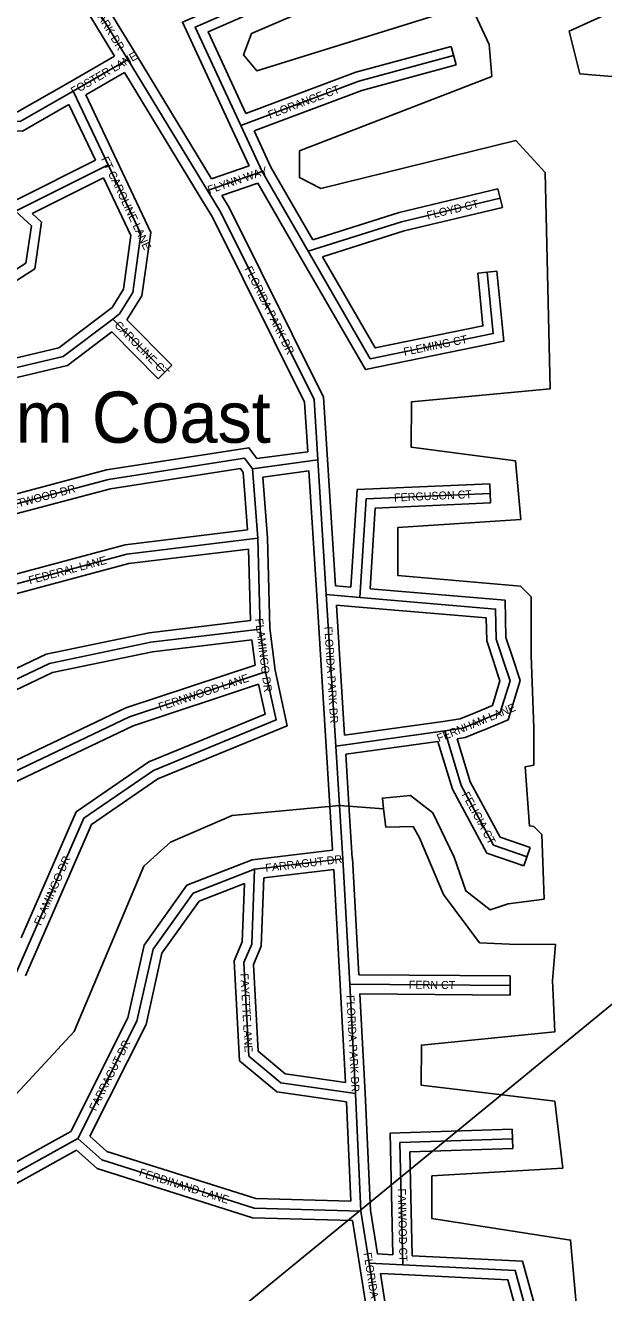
# Model space of a CAD drawing. Extents: x 457167 to 656239, y 1787309 to 1969297.
# Drawn here: x 588703 to 590509, y 1900964 to 1904923 of the extents above; entities that cross this region are included whole.
import ezdxf

# ---------------------------------------------------------------- set-up
doc = ezdxf.new("R2010")
doc.units = 0
for name, color, linetype in [('Level 1', 7, 'Continuous'), ('Level 31', 7, 'Continuous'), ('Level 32', 7, 'Continuous'), ('Level 34', 7, 'Continuous'), ('Level 44', 7, 'Continuous'), ('Level 5', 7, 'Continuous')]:
    doc.layers.add(name, color=color, linetype=linetype)

msp = doc.modelspace()

# ---------------------------------------------------------------- linework, layer by layer
at = {"layer": 'Level 1'}
msp.add_line((587876.128, 1899689.718), (592117.707, 1903161.447), dxfattribs=at)
at = {"layer": 'Level 31'}
for p, q in [((589023.1, 1904816), (588811.694, 1905163.662)), ((588852.212, 1904717.765), (589023.1, 1904816)), ((589271.277, 1904407.545), (589023.1, 1904816)), ((588961.153, 1904487.746), (588852.212, 1904717.765)), ((589442.73, 1904466.145), (589375.913, 1904610.268)), ((588672.237, 1904342.815), (588961.153, 1904487.746)), ((589271.277, 1904407.545), (589442.73, 1904466.145)), ((589442.73, 1904466.145), (589586.293, 1904217.52)), ((588975.539, 1904005.531), (589138.643, 1903840.141)), ((589412.132, 1903537.461), (589616.279, 1903565.456)), ((589642.549, 1903145.041), (589616.279, 1903565.456)), ((589412.132, 1903537.461), (589428.592, 1903320.701)), ((589436.349, 1903037.411), (589428.592, 1903320.701)), ((589671.903, 1902671.89), (589642.549, 1903145.041)), ((589642.549, 1903145.041), (589747.442, 1903135.761)), ((589452.959, 1902903.924), (589436.349, 1903037.411)), ((590012.155, 1902719.281), (589671.903, 1902671.89)), ((589683.334, 1902486.413), (589671.903, 1902671.89)), ((589693.845, 1902319.846), (589683.334, 1902486.413)), ((589418.469, 1902286.888), (589693.845, 1902319.846)), ((589715.716, 1901927.802), (589693.845, 1902319.846)), ((589734.181, 1901586.31), (589715.716, 1901927.802)), ((589715.716, 1901927.802), (590216.434, 1901923.996)), ((589750.375, 1901219.368), (589734.181, 1901586.31)), ((588057.643, 1900996.989), (588866.949, 1901446.058)), ((589776.154, 1901056.774), (589750.375, 1901219.368)), ((589808.218, 1900852.351), (589776.154, 1901056.774)), ((589776.154, 1901056.774), (589881.061, 1901051.131))]:
    msp.add_line(p, q, dxfattribs=at)
for points in [[(589375.913, 1904610.268), (589233.094, 1904917.44), (589568.101, 1905064.472), (589897.018, 1905184.975)], [(589375.913, 1904610.268), (589743.967, 1904748.516), (590040.07, 1904828.35)], [(587589.934, 1904249.169), (588194.334, 1904635.694), (588686.098, 1904622.793), (588852.212, 1904717.765)], [(588975.539, 1904005.531), (588996.232, 1904021.493), (589037.998, 1904088.326), (589063.125, 1904271.556), (588961.153, 1904487.746)], [(589616.279, 1903565.456), (589604.218, 1903753.844), (589313.433, 1904338.013), (589271.277, 1904407.545)], [(589586.293, 1904217.52), (589877.654, 1904309.724), (590185.512, 1904383.356)], [(587829.185, 1903834.538), (588079.039, 1903998.08), (588613.024, 1904122.192), (588704.687, 1904180.571), (588721.429, 1904297.27), (588672.237, 1904342.815)], [(589586.293, 1904217.52), (589779.93, 1903881.53), (590164.098, 1903960.48), (590145.364, 1904151.788)], [(587978.125, 1903575.714), (588262.027, 1903755.921), (588820.826, 1903888.356), (588975.539, 1904005.531)], [(588166.999, 1903249.181), (588461.609, 1903372.277), (588961.918, 1903504.821), (589387.396, 1903570.961), (589412.132, 1903537.461)], [(589747.442, 1903135.761), (589767.386, 1903444.092), (590153.992, 1903461.218)], [(588267.949, 1902995.536), (588619.547, 1903163.622), (589019.99, 1903271.258), (589428.592, 1903320.701)], [(589747.442, 1903135.761), (590171.152, 1903099.729), (590173.21, 1903005.542), (590195.029, 1902939.684)], [(587807.099, 1902370.559), (587826.512, 1902381.07), (588202.155, 1902655.653), (588777.76, 1902929.876), (589094.52, 1902996.21), (589436.349, 1903037.411)], [(590195.029, 1902939.684), (590216.216, 1902876.01), (590185.838, 1902776.426), (590121.254, 1902749.268)], [(588590.73, 1902526.576), (588643.919, 1902579.933), (589027.655, 1902762.874), (589452.959, 1902903.924)], [(588675.231, 1901966.051), (588885.293, 1902446.401), (589102.381, 1902595.827), (589486.069, 1902753.681), (589452.959, 1902903.924)], [(590121.254, 1902749.268), (590068.44, 1902727.543), (590012.155, 1902719.281)], [(590012.155, 1902719.281), (590063.989, 1902548.276), (590164.756, 1902362.276), (590269.604, 1902326.089)], [(588866.949, 1901446.058), (589051.054, 1901812.274), (589101.373, 1902037.276), (589226.631, 1902212.324), (589418.469, 1902286.888)], [(589734.181, 1901586.31), (589500.884, 1901619.821), (589400.889, 1901703.64), (589384.882, 1901995.308), (589409.784, 1902053.446), (589418.469, 1902286.888)], [(589750.375, 1901219.368), (589416.885, 1901228.331), (588941.858, 1901379.011), (588866.949, 1901446.058)], [(589881.061, 1901051.131), (589872.522, 1901433.333), (590223.85, 1901445.068)], [(589881.061, 1901051.131), (590232.023, 1901033.776), (590348.274, 1900612.473), (590536.846, 1900093.951), (590398.49, 1899884.376)]]:
    msp.add_lwpolyline(points, dxfattribs=at)
at = {"layer": 'Level 32'}
for p, q in [((588981.492, 1904826.684), (588786.062, 1905148.075)), ((589048.734, 1904831.587), (588855.181, 1905149.89)), ((588837.26, 1904743.773), (588981.492, 1904826.684)), ((589284.394, 1904443.731), (589048.739, 1904831.578)), ((590032.261, 1904857.316), (590047.88, 1904799.383)), ((588891.187, 1904705.563), (589012.668, 1904775.397)), ((589245.639, 1904391.966), (589012.667, 1904775.396)), ((588988.266, 1904500.586), (588891.186, 1904705.563)), ((588921.486, 1904501.41), (588838.971, 1904675.634)), ((589401.499, 1904483.756), (589348.696, 1904597.649)), ((589469.383, 1904479.982), (589416.73, 1904593.551)), ((588677.484, 1904379.009), (588921.486, 1904501.41)), ((589284.394, 1904443.731), (589401.499, 1904483.756)), ((589469.384, 1904479.982), (589600.221, 1904253.394)), ((588724.391, 1904335.412), (588947.132, 1904447.146)), ((589316.262, 1904391.214), (589429.088, 1904429.776)), ((589429.088, 1904429.776), (589560.313, 1904202.517)), ((590178.533, 1904412.535), (590192.49, 1904354.178)), ((590115.506, 1904148.865), (590175.221, 1904154.711)), ((589020.097, 1904003.074), (589160.004, 1903861.207)), ((588972.665, 1903965.718), (589117.283, 1903819.075)), ((589160.004, 1903861.207), (589117.283, 1903819.075)), ((589425.694, 1903569.601), (589584.558, 1903591.387)), ((589670.883, 1903172.651), (589646.221, 1903567.326)), ((589382.873, 1903526.582), (589396.506, 1903347.037)), ((589444.185, 1903511.573), (589588.352, 1903531.344)), ((589612.606, 1903143.183), (589588.352, 1903531.345)), ((589444.185, 1903511.573), (589458.562, 1903322.247)), ((590152.664, 1903491.19), (590155.319, 1903431.246)), ((589466.299, 1903039.677), (589458.563, 1903322.247)), ((589405.613, 1903063.923), (589399.505, 1903286.961)), ((589670.883, 1903172.651), (589719.488, 1903168.351)), ((589641.96, 1902670.032), (589612.606, 1903143.183)), ((589674.652, 1903112.082), (589744.799, 1903105.876)), ((589699.841, 1902706.071), (589674.652, 1903112.081)), ((589420.149, 1902924.649), (589410.269, 1903004.048)), ((589482.558, 1902909.014), (589466.299, 1903039.677)), ((590007.798, 1902748.963), (589699.841, 1902706.071)), ((589990.888, 1902686.027), (589703.556, 1902646.008)), ((589653.391, 1902484.567), (589641.959, 1902670.044)), ((589713.277, 1902488.258), (589703.556, 1902646.008)), ((589723.786, 1902321.736), (589713.274, 1902488.301)), ((589662.119, 1902346.264), (589653.394, 1902484.524)), ((589411.138, 1902316.225), (589662.119, 1902346.263)), ((590279.391, 1902354.448), (590259.816, 1902297.73)), ((589744.103, 1901957.587), (589723.799, 1902321.517)), ((589447.496, 1902260.146), (589665.672, 1902286.259)), ((589685.762, 1901926.131), (589665.673, 1902286.259)), ((589744.102, 1901957.587), (590216.662, 1901953.996)), ((590216.662, 1901953.996), (590216.207, 1901893.996)), ((589702.251, 1901621.205), (589685.759, 1901926.182)), ((589764.153, 1901587.632), (589747.396, 1901897.559)), ((589747.397, 1901897.559), (590216.207, 1901893.996)), ((589780.273, 1901222.386), (589764.153, 1901587.632)), ((589718.984, 1901250.223), (589705.307, 1901560.148)), ((588046.048, 1901024.863), (588844.303, 1901467.8)), ((590222.848, 1901475.052), (590224.852, 1901415.085)), ((588097.979, 1900985.061), (588862.844, 1901409.47)), ((589801.987, 1901085.427), (589780.272, 1901222.386)), ((589746.525, 1901052.076), (589724.65, 1901190.047)), ((589801.987, 1901085.428), (589850.345, 1901082.827)), ((589778.419, 1900848.731), (589746.517, 1901052.126)), ((589835.007, 1900875.166), (589811.534, 1901024.826)), ((589811.534, 1901024.826), (589879.45, 1901021.173))]:
    msp.add_line(p, q, dxfattribs=at)
for points in [[(589348.709, 1904597.619), (589192.965, 1904932.591), (589556.901, 1905092.32), (589886.697, 1905213.144)], [(589391.394, 1904648.129), (589273.224, 1904902.288), (589579.3, 1905036.625), (589907.339, 1905156.805)], [(589391.394, 1904648.13), (589734.766, 1904777.107), (590032.261, 1904857.316)], [(589416.731, 1904593.551), (589753.167, 1904719.924), (590047.88, 1904799.383)], [(587573.77, 1904274.444), (588185.923, 1904665.926), (588678.494, 1904653.004), (588837.321, 1904743.809)], [(587630.253, 1904239.342), (588202.746, 1904605.462), (588693.702, 1904592.582), (588838.971, 1904675.635)], [(589020.097, 1904003.074), (589066.847, 1904077.88), (589094.057, 1904276.301), (588988.286, 1904500.544)], [(588957.427, 1904029.446), (588973.644, 1904041.959), (589009.149, 1904098.774), (589032.193, 1904266.811), (588947.133, 1904447.147)], [(589584.558, 1903591.387), (589574.665, 1903745.891), (589287.131, 1904323.527), (589245.624, 1904391.991)], [(589646.218, 1903567.373), (589633.77, 1903761.798), (589339.734, 1904352.5), (589316.262, 1904391.214)], [(589600.221, 1904253.394), (589869.629, 1904338.651), (590178.533, 1904412.535)], [(589630.916, 1904200.172), (589885.68, 1904280.796), (590192.49, 1904354.178)], [(587869.317, 1903824.949), (588091.016, 1903970.063), (588624.814, 1904094.131), (588732.425, 1904162.67), (588753.361, 1904308.59), (588724.39, 1904335.412)], [(589560.313, 1904202.517), (589764.753, 1903847.783), (590196.586, 1903936.528), (590175.221, 1904154.711)], [(589630.916, 1904200.172), (589795.107, 1903915.276), (590131.609, 1903984.431), (590115.506, 1904148.865)], [(587988.5, 1903617.833), (588250.205, 1903783.951), (588807.755, 1903916.09), (588957.427, 1904029.446)], [(588018.51, 1903565.812), (588273.849, 1903727.891), (588833.898, 1903860.622), (588972.665, 1903965.718)], [(588179.766, 1903287.028), (588451.939, 1903400.751), (588955.755, 1903534.225), (589400.739, 1903603.396), (589425.693, 1903569.601)], [(588205.781, 1903232.869), (588471.278, 1903343.803), (588968.079, 1903475.418), (589374.054, 1903538.526), (589382.873, 1903526.582)], [(589719.488, 1903168.351), (589739.184, 1903472.873), (590152.664, 1903491.19)], [(589779.278, 1903163.161), (589795.588, 1903415.312), (590155.319, 1903431.246)], [(588283.959, 1903036.441), (588609.095, 1903191.879), (589014.266, 1903300.785), (589396.506, 1903347.037)], [(588280.889, 1902968.47), (588629.998, 1903135.366), (589025.715, 1903241.731), (589399.505, 1903286.961)], [(589779.278, 1903163.161), (590200.556, 1903127.337), (590203.105, 1903010.701), (590223.508, 1902949.119)], [(589744.9, 1903105.867), (590141.748, 1903072.121), (590143.316, 1903000.384), (590166.55, 1902930.25)], [(587817.915, 1902411.947), (588186.719, 1902681.531), (588768.099, 1902958.504), (589089.642, 1903025.84), (589405.613, 1903063.922)], [(587847.989, 1902359.606), (588217.593, 1902629.776), (588787.423, 1902901.248), (589099.399, 1902966.58), (589410.269, 1903004.047)], [(588569.566, 1902547.84), (588626.331, 1902604.784), (589016.434, 1902790.761), (589420.15, 1902924.648)], [(590166.563, 1902930.212), (590184.73, 1902875.615), (590161.247, 1902798.631), (590109.624, 1902776.922)], [(590223.495, 1902949.156), (590247.703, 1902876.405), (590210.429, 1902754.221), (590132.882, 1902721.613)], [(588702.719, 1901954.03), (588909.351, 1902426.541), (589116.755, 1902569.3), (589520.791, 1902735.524), (589482.558, 1902909.014)], [(588622.649, 1902516.101), (588661.507, 1902555.083), (589038.876, 1902734.987), (589430.823, 1902864.975)], [(588689.4, 1902073.322), (588861.234, 1902466.262), (589088.007, 1902622.354), (589451.349, 1902771.836), (589430.824, 1902864.973)], [(590109.84, 1902777.013), (590060.437, 1902756.691), (590007.798, 1902748.963)], [(589990.888, 1902686.027), (590036.161, 1902536.662), (590143.937, 1902337.725), (590259.816, 1902297.73)], [(590132.666, 1902721.522), (590076.444, 1902698.396), (590050.968, 1902694.655)], [(590050.969, 1902694.655), (590091.816, 1902559.891), (590185.575, 1902386.827), (590279.391, 1902354.448)], [(588844.302, 1901467.801), (589022.585, 1901822.438), (589073.426, 1902049.776), (589207.434, 1902237.05), (589411.138, 1902316.225)], [(589702.251, 1901621.205), (589513.608, 1901648.302), (589430.133, 1901718.274), (589415.222, 1901989.946), (589439.556, 1902046.758), (589447.497, 1902260.146)], [(588904.068, 1901453.097), (589079.522, 1901802.11), (589129.319, 1902024.776), (589245.829, 1902187.599), (589386.793, 1902242.387)], [(589705.307, 1901560.148), (589488.162, 1901591.341), (589371.647, 1901689.005), (589354.543, 1902000.671), (589380.012, 1902060.133), (589386.793, 1902242.387)], [(589850.345, 1901082.827), (589841.866, 1901462.326), (590222.848, 1901475.052)], [(589718.984, 1901250.222), (589421.922, 1901258.208), (588957.067, 1901405.661), (588904.068, 1901453.097)], [(589724.649, 1901190.047), (589411.849, 1901198.455), (588926.649, 1901352.363), (588862.844, 1901409.47)], [(589910.432, 1901079.716), (589903.178, 1901404.339), (590224.852, 1901415.085)], [(589910.431, 1901079.716), (590255.172, 1901062.668), (590376.876, 1900621.604), (590570.199, 1900090.018), (590422.44, 1899866.198)], [(589879.579, 1901021.167), (590208.874, 1901004.883), (590319.672, 1900603.342), (590503.494, 1900097.883), (590409.674, 1899955.766)]]:
    msp.add_lwpolyline(points, dxfattribs=at)
at = {"layer": 'Level 5'}
for p, q in [((589683.334, 1902486.413), (589821.608, 1902475.983)), ((590210.211, 1902179.283), (590323.358, 1902193.498))]:
    msp.add_line(p, q, dxfattribs=at)
for points in [[(590277.085, 1902421.35), (590263.108, 1902606.831), (590290.373, 1902612.541), (590290.501, 1902729.254), (590282.398, 1902954.329), (590282.585, 1903137.734), (590249.274, 1903171.144), (589865.839, 1903204.883), (589865.997, 1903354.936), (590249.501, 1903379.55), (590233.029, 1903562.954), (589907.944, 1903604.993), (589908.102, 1903746.716), (590341.617, 1903787.94), (590325.658, 1904463.186), (590234.095, 1904563.318), (589625.379, 1904413.911), (589558.728, 1904447.321), (589558.786, 1904530.693), (590159.261, 1904763.492), (590151.019, 1904863.525), (590092.797, 1904988.637), (589425.701, 1904780.949), (589384.05, 1904831), (589409.129, 1904897.651), (590009.634, 1905155.461)], [(591159.901, 1905045.844), (590534.396, 1904763.064), (590434.354, 1904771.534), (590401.173, 1904904.947), (590784.835, 1905079.583)], [(586678.859, 1900832.42), (587395.936, 1900981.716), (587887.911, 1901106.242), (588646.995, 1901555.587), (588855.624, 1901780.444), (589072.92, 1902297.067), (589156.38, 1902372), (589348.212, 1902455.162), (589683.334, 1902486.413)], [(589821.608, 1902475.983), (589817.535, 1902509.081), (589905.612, 1902517.286), (589975.458, 1902463.706), (590041.337, 1902325.042), (590078.664, 1902219.156), (590154.223, 1902159.747), (590210.211, 1902179.283)], [(590214.757, 1902053.456), (590120.977, 1902057.26), (590008.066, 1902208.009), (589933.67, 1902384.871), (589913.387, 1902420.181), (589828.499, 1902418.151), (589821.608, 1902475.983)], [(590323.358, 1902193.498), (590315.156, 1902395.766), (590290.145, 1902420.806), (590276.973, 1902422.848)], [(590349.35, 1901939.669), (590358.135, 1902052.11), (590214.757, 1902053.456)], [(590745.986, 1899911.068), (590454.933, 1900569.973), (590405.494, 1901128.536), (589972.068, 1901195.686), (589972.236, 1901329.068), (590380.741, 1901353.651), (590355.928, 1901562.096), (589939.181, 1901612.575), (589939.309, 1901737.618), (590356.154, 1901778.841), (590349.35, 1901939.669)]]:
    msp.add_lwpolyline(points, dxfattribs=at)

# ---------------------------------------------------------------- texts
at = {"layer": 'Level 34'}
for s, height, rotation, p in [('FLORIDA PARK DR', 25, 301.302525, (588835.534, 1905100.401)), ('FOSTER LANE', 25, 29.892031, (588853.777, 1904704.246)), ('FLORANCE CT', 25, 20.586522, (589466.15, 1904630.811)), ('FT CAROLINE LANE', 25, 295.252111, (588938.758, 1904505.925)), ('FLYNN WAY', 25, 18.869133, (589277, 1904396.292)), ('FLOYD CT', 25, 13.450606, (589959.595, 1904316.471)), ('FLORIDA PARK DR', 25, 296.462592, (589386.583, 1904163.011)), ('CAROLINE CT', 25, 314.601119, (588978.859, 1903984.363)), ('FLEMING CT', 25, 11.612628, (589886.604, 1903890.691)), ('FLEETWOOD DR', 25, 14.837639, (588600.792, 1903396.221)), ('FERGUSON CT', 25, 2.536156, (589854.574, 1903435.443)), ('FEDERAL LANE', 25, 15.044533, (588716.708, 1903176.796)), ('FLAMINGO DR', 25, 277.092117, (589419.825, 1903068.984)), ('FLORIDA PARK DR', 25, 273.549394, (589636.268, 1903044.436)), ('FERNWOOD LANE', 24.99916, 18.347378, (589123.172, 1902781.384)), ('FERNHAM LANE', 25, 22.359019, (589993.866, 1902683.353)), ('FELICIA CT', 25, 298.446414, (590064.899, 1902520.356)), ('FLAMINGO DR', 25, 66.378903, (588751.394, 1902109.018)), ('FARRAGUT DR', 24.99916, 6.824739, (589453.508, 1902278.493)), ('FAYETTE LANE', 25, 273.140686, (589374.244, 1901961.061)), ('FERN CT', 25, 359.564272, (589900.313, 1901913.9)), ('FLORIDA PARK DR', 25, 273.094267, (589705.071, 1901893.19)), ('FARRAGUT DR', 25, 63.30945, (588923.059, 1901529.846)), ('FERDINAND LANE', 25, 342.400633, (589055.805, 1901329.755)), ('FANWOOD CT', 25, 271.278964, (589865.825, 1901289.341)), ('FLORIDA PARK DR', 25, 278.913483, (589758.609, 1901087.978))]:
    msp.add_text(s, height=height, rotation=rotation, dxfattribs=at).set_placement(p)
at = {"layer": 'Level 44'}
msp.add_text('Palm Coast', height=160, dxfattribs=at).set_placement((588363.425, 1903619.156))

doc.saveas('drawing.dxf')
